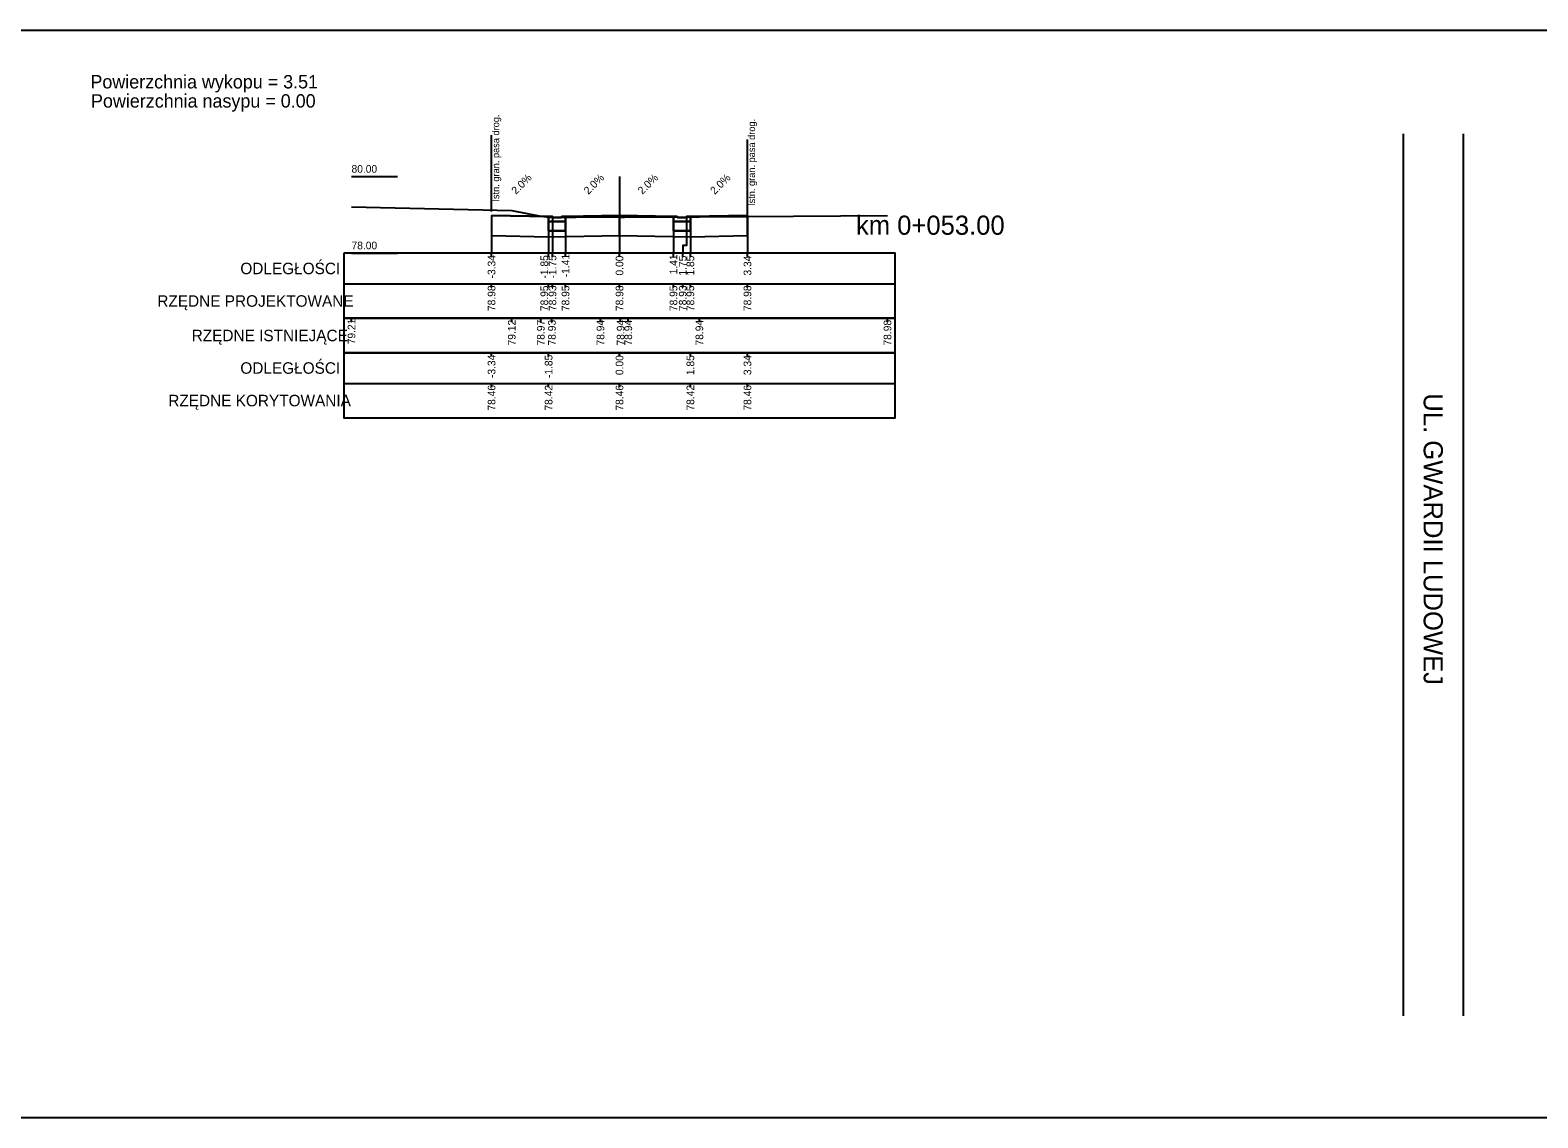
# Model space of a CAD drawing. Extents: x 7492871 to 7493499, y 5802964 to 5802992.
# Drawn here: x 7493262.74 to 7493302.12, y 5802963.88 to 5802992.28 of the extents above; entities that cross this region are included whole.
import ezdxf

# ---------------------------------------------------------------- set-up
doc = ezdxf.new("R2010")
doc.units = 0
for name, color, linetype in [('_wydruk', 7, 'Continuous'), ('d_pop_nasyp_opis', 7, 'Continuous'), ('d_pop_wykop_opis', 7, 'Continuous'), ('opisy_ramki_pop', 7, 'Continuous'), ('pop_comp_kostka', 7, 'Continuous'), ('pop_comp_lawa', 7, 'Continuous'), ('pop_comp_scieralna', 7, 'Continuous'), ('pop_granica_istn', 7, 'Continuous'), ('pop_opis', 7, 'Continuous'), ('pop_os', 7, 'Continuous'), ('pop_pikietaz', 7, 'Continuous'), ('pop_teren', 7, 'Continuous')]:
    doc.layers.add(name, color=color, linetype=linetype)

msp = doc.modelspace()

# ---------------------------------------------------------------- linework, layer by layer
msp.add_lwpolyline([(7493274.794, 5802987.442), (7493276.285, 5802987.413), (7493276.385, 5802987.413), (7493276.386, 5802987.393), (7493276.625, 5802987.393), (7493276.626, 5802987.413), (7493276.726, 5802987.413), (7493278.136, 5802987.441), (7493279.546, 5802987.413), (7493279.646, 5802987.413), (7493279.647, 5802987.393), (7493279.886, 5802987.393), (7493279.887, 5802987.413), (7493279.987, 5802987.413), (7493281.478, 5802987.442)])
at = {"layer": '_wydruk'}
msp.add_lwpolyline([(7492871.369, 5802992.281), (7493499.283, 5802992.281), (7493499.283, 5802963.881), (7492871.369, 5802963.881)], close=True, dxfattribs=at)
at = {"layer": 'opisy_ramki_pop'}
for p, q in [((7493298.607, 5802989.573), (7493298.607, 5802966.547)), ((7493300.173, 5802989.573), (7493300.173, 5802966.547))]:
    msp.add_line(p, q, dxfattribs=at)
for points in [[(7493274.794, 5802986.922), (7493274.794, 5802986.659), (7493274.794, 5802986.659), (7493274.794, 5802986.459)], [(7493276.285, 5802986.884), (7493276.285, 5802986.659), (7493276.285, 5802986.659), (7493276.285, 5802986.459)], [(7493278.136, 5802986.921), (7493278.136, 5802986.659), (7493278.136, 5802986.659), (7493278.136, 5802986.459)], [(7493279.987, 5802986.884), (7493279.987, 5802986.659), (7493279.987, 5802986.659), (7493279.987, 5802986.459)], [(7493281.478, 5802986.922), (7493281.478, 5802986.659), (7493281.478, 5802986.659), (7493281.478, 5802986.459)]]:
    msp.add_lwpolyline(points, dxfattribs=at)
at = {"layer": 'pop_comp_kostka'}
for p, q in [((7493276.385, 5802987.413), (7493276.285, 5802987.413)), ((7493276.285, 5802987.413), (7493276.285, 5802987.283)), ((7493276.386, 5802987.393), (7493276.385, 5802987.413)), ((7493276.625, 5802987.393), (7493276.386, 5802987.393)), ((7493276.626, 5802987.413), (7493276.625, 5802987.393)), ((7493276.726, 5802987.413), (7493276.626, 5802987.413)), ((7493276.726, 5802987.283), (7493276.726, 5802987.413)), ((7493279.646, 5802987.413), (7493279.546, 5802987.413)), ((7493279.546, 5802987.413), (7493279.546, 5802987.283)), ((7493279.647, 5802987.393), (7493279.646, 5802987.413)), ((7493279.886, 5802987.393), (7493279.647, 5802987.393)), ((7493279.887, 5802987.413), (7493279.886, 5802987.393)), ((7493279.987, 5802987.413), (7493279.887, 5802987.413)), ((7493279.987, 5802987.283), (7493279.987, 5802987.413)), ((7493276.285, 5802987.283), (7493276.726, 5802987.283)), ((7493279.546, 5802987.283), (7493279.987, 5802987.283))]:
    msp.add_line(p, q, dxfattribs=at)
at = {"layer": 'pop_comp_lawa'}
for p, q in [((7493276.726, 5802987.283), (7493276.285, 5802987.283)), ((7493276.285, 5802987.283), (7493276.285, 5802987.042)), ((7493276.285, 5802987.042), (7493276.726, 5802987.042)), ((7493276.726, 5802987.042), (7493276.726, 5802987.283)), ((7493279.987, 5802987.283), (7493279.546, 5802987.283)), ((7493279.546, 5802987.283), (7493279.546, 5802987.042)), ((7493279.546, 5802987.042), (7493279.987, 5802987.042)), ((7493279.987, 5802987.042), (7493279.987, 5802987.283))]:
    msp.add_line(p, q, dxfattribs=at)
at = {"layer": 'pop_comp_scieralna'}
for p, q in [((7493276.285, 5802987.413), (7493274.794, 5802987.442)), ((7493274.794, 5802987.442), (7493274.794, 5802986.922)), ((7493276.285, 5802987.042), (7493276.285, 5802987.413)), ((7493278.136, 5802987.441), (7493276.726, 5802987.413)), ((7493276.726, 5802987.413), (7493276.726, 5802987.042)), ((7493278.136, 5802986.921), (7493278.136, 5802987.441)), ((7493279.546, 5802987.413), (7493278.136, 5802987.441)), ((7493278.136, 5802987.441), (7493278.136, 5802986.921)), ((7493279.546, 5802987.042), (7493279.546, 5802987.413)), ((7493281.478, 5802987.442), (7493279.987, 5802987.413)), ((7493279.987, 5802987.413), (7493279.987, 5802987.042)), ((7493281.478, 5802986.922), (7493281.478, 5802987.442)), ((7493276.726, 5802987.042), (7493276.285, 5802987.042)), ((7493279.987, 5802987.042), (7493279.546, 5802987.042)), ((7493274.794, 5802986.922), (7493276.285, 5802986.884)), ((7493276.285, 5802986.884), (7493278.136, 5802986.921)), ((7493278.136, 5802986.921), (7493279.987, 5802986.884)), ((7493279.987, 5802986.884), (7493281.478, 5802986.922))]:
    msp.add_line(p, q, dxfattribs=at)
at = {"layer": 'pop_granica_istn'}
for p, q in [((7493274.794, 5802988.043), (7493274.794, 5802989.543)), ((7493281.478, 5802987.928), (7493281.478, 5802989.428)), ((7493274.794, 5802987.543), (7493274.794, 5802988.043)), ((7493281.478, 5802987.428), (7493281.478, 5802987.928))]:
    msp.add_line(p, q, dxfattribs=at)
at = {"layer": 'pop_opis'}
for p, q in [((7493271.136, 5802988.459), (7493272.336, 5802988.459)), ((7493270.936, 5802986.459), (7493270.936, 5802984.759)), ((7493270.936, 5802986.459), (7493270.936, 5802984.759)), ((7493270.936, 5802986.459), (7493270.936, 5802984.759)), ((7493270.936, 5802986.459), (7493270.936, 5802984.759)), ((7493271.136, 5802986.459), (7493272.336, 5802986.459)), ((7493274.794, 5802986.359), (7493274.794, 5802986.459)), ((7493276.285, 5802986.359), (7493276.285, 5802986.459)), ((7493276.386, 5802986.359), (7493276.386, 5802986.459)), ((7493276.726, 5802986.359), (7493276.726, 5802986.459)), ((7493278.136, 5802986.359), (7493278.136, 5802986.459)), ((7493279.546, 5802986.359), (7493279.546, 5802986.459)), ((7493279.787, 5802986.359), (7493279.787, 5802986.459)), ((7493279.987, 5802986.359), (7493279.987, 5802986.459)), ((7493281.478, 5802986.359), (7493281.478, 5802986.459)), ((7493270.936, 5802985.659), (7493285.336, 5802985.659)), ((7493270.936, 5802985.659), (7493285.336, 5802985.659)), ((7493270.936, 5802985.659), (7493285.336, 5802985.659)), ((7493270.936, 5802985.659), (7493285.336, 5802985.659)), ((7493274.794, 5802985.559), (7493274.794, 5802985.659)), ((7493276.285, 5802985.559), (7493276.285, 5802985.659)), ((7493276.386, 5802985.559), (7493276.386, 5802985.659)), ((7493276.726, 5802985.559), (7493276.726, 5802985.659)), ((7493278.136, 5802985.559), (7493278.136, 5802985.659)), ((7493279.546, 5802985.559), (7493279.546, 5802985.659)), ((7493279.787, 5802985.559), (7493279.787, 5802985.659)), ((7493279.987, 5802985.559), (7493279.987, 5802985.659)), ((7493281.478, 5802985.559), (7493281.478, 5802985.659)), ((7493270.936, 5802984.759), (7493270.936, 5802983.859)), ((7493271.136, 5802984.659), (7493271.136, 5802984.759)), ((7493275.322, 5802984.659), (7493275.322, 5802984.759)), ((7493276.08, 5802984.659), (7493276.08, 5802984.759)), ((7493276.37, 5802984.659), (7493276.37, 5802984.759)), ((7493277.638, 5802984.659), (7493277.638, 5802984.759)), ((7493278.165, 5802984.659), (7493278.165, 5802984.759)), ((7493278.365, 5802984.659), (7493278.365, 5802984.759)), ((7493280.222, 5802984.659), (7493280.222, 5802984.759)), ((7493285.136, 5802984.659), (7493285.136, 5802984.759)), ((7493270.936, 5802983.859), (7493270.936, 5802982.159)), ((7493274.794, 5802983.759), (7493274.794, 5802983.859)), ((7493276.285, 5802983.759), (7493276.285, 5802983.859)), ((7493278.136, 5802983.759), (7493278.136, 5802983.859)), ((7493279.987, 5802983.759), (7493279.987, 5802983.859)), ((7493281.478, 5802983.759), (7493281.478, 5802983.859)), ((7493270.936, 5802983.059), (7493285.336, 5802983.059)), ((7493274.794, 5802982.959), (7493274.794, 5802983.059)), ((7493276.285, 5802982.959), (7493276.285, 5802983.059)), ((7493278.136, 5802982.959), (7493278.136, 5802983.059)), ((7493279.987, 5802982.959), (7493279.987, 5802983.059)), ((7493281.478, 5802982.959), (7493281.478, 5802983.059))]:
    msp.add_line(p, q, dxfattribs=at)
for points in [[(7493274.794, 5802987.442), (7493274.794, 5802986.659), (7493274.794, 5802986.659), (7493274.794, 5802986.459)], [(7493276.285, 5802987.413), (7493276.285, 5802986.659), (7493276.285, 5802986.659), (7493276.285, 5802986.459)], [(7493276.386, 5802987.393), (7493276.386, 5802986.659), (7493276.386, 5802986.659), (7493276.386, 5802986.459)], [(7493276.726, 5802987.413), (7493276.726, 5802986.659), (7493276.726, 5802986.659), (7493276.726, 5802986.459)], [(7493278.136, 5802987.441), (7493278.136, 5802986.659), (7493278.136, 5802986.659), (7493278.136, 5802986.459)], [(7493279.546, 5802987.413), (7493279.546, 5802986.659), (7493279.546, 5802986.659), (7493279.546, 5802986.459)], [(7493279.886, 5802987.393), (7493279.886, 5802986.659), (7493279.787, 5802986.659), (7493279.787, 5802986.459)], [(7493279.987, 5802987.413), (7493279.987, 5802986.659), (7493279.987, 5802986.659), (7493279.987, 5802986.459)], [(7493281.478, 5802987.442), (7493281.478, 5802986.659), (7493281.478, 5802986.659), (7493281.478, 5802986.459)]]:
    msp.add_lwpolyline(points, dxfattribs=at)
for points in [[(7493270.936, 5802986.459), (7493270.936, 5802984.759), (7493285.336, 5802984.759), (7493285.336, 5802986.459)], [(7493270.936, 5802986.459), (7493270.936, 5802984.759), (7493285.336, 5802984.759), (7493285.336, 5802986.459)], [(7493270.936, 5802986.459), (7493270.936, 5802984.759), (7493285.336, 5802984.759), (7493285.336, 5802986.459)], [(7493270.936, 5802986.459), (7493270.936, 5802984.759), (7493285.336, 5802984.759), (7493285.336, 5802986.459)], [(7493270.936, 5802984.759), (7493270.936, 5802983.859), (7493285.336, 5802983.859), (7493285.336, 5802984.759)], [(7493270.936, 5802983.859), (7493270.936, 5802982.159), (7493285.336, 5802982.159), (7493285.336, 5802983.859)]]:
    msp.add_lwpolyline(points, close=True, dxfattribs=at)
at = {"layer": 'pop_os'}
msp.add_line((7493278.136, 5802988.459), (7493278.136, 5802986.459), dxfattribs=at)
at = {"layer": 'pop_teren'}
msp.add_lwpolyline([(7493271.136, 5802987.665), (7493275.322, 5802987.576), (7493276.08, 5802987.428), (7493276.37, 5802987.387), (7493277.638, 5802987.403), (7493278.165, 5802987.399), (7493278.27, 5802987.4), (7493280.222, 5802987.404), (7493285.136, 5802987.442)], dxfattribs=at)

# ---------------------------------------------------------------- texts
at = {"layer": 'd_pop_nasyp_opis'}
msp.add_text('Powierzchnia nasypu = 0.00', height=0.35, dxfattribs=at).set_placement((7493264.331, 5802990.259))
at = {"layer": 'd_pop_wykop_opis'}
msp.add_text('Powierzchnia wykopu = 3.51', height=0.35, dxfattribs=at).set_placement((7493264.316, 5802990.759))
at = {"layer": 'pop_granica_istn'}
for p in [(7493274.993, 5802987.804), (7493281.677, 5802987.69)]:
    msp.add_text('Istn. gran. pasa drog.', height=0.18, rotation=90, dxfattribs=at).set_placement(p)
at = {"layer": 'pop_opis'}
for s, height, p in [('80.00', 0.2, (7493271.136, 5802988.559)), ('78.00', 0.2, (7493271.136, 5802986.559)), ('ODLEGŁOŚCI', 0.3, (7493268.232, 5802985.909)), ('ODLEGŁOŚCI', 0.3, (7493268.232, 5802985.909)), ('ODLEGŁOŚCI', 0.3, (7493268.232, 5802985.909)), ('ODLEGŁOŚCI', 0.3, (7493268.232, 5802985.909)), ('RZĘDNE PROJEKTOWANE', 0.3, (7493266.064, 5802985.059)), ('RZĘDNE PROJEKTOWANE', 0.3, (7493266.064, 5802985.059)), ('RZĘDNE PROJEKTOWANE', 0.3, (7493266.064, 5802985.059)), ('RZĘDNE PROJEKTOWANE', 0.3, (7493266.064, 5802985.059)), ('RZĘDNE ISTNIEJĄCE', 0.3, (7493266.961, 5802984.159)), ('ODLEGŁOŚCI', 0.3, (7493268.232, 5802983.309)), ('RZĘDNE KORYTOWANIA', 0.3, (7493266.35, 5802982.459))]:
    msp.add_text(s, height=height, dxfattribs=at).set_placement(p)
for s, rotation, p in [('2.0%', 45, (7493275.431, 5802987.977)), ('2.0%', 45, (7493277.322, 5802987.977)), ('2.0%', 45, (7493278.732, 5802987.977)), ('2.0%', 45, (7493280.624, 5802987.977)), ('-3.34', 90, (7493274.894, 5802985.798)), ('-1.85', 90, (7493276.272, 5802985.796)), ('-1.75', 90, (7493276.486, 5802985.796)), ('-1.41', 90, (7493276.826, 5802985.829)), ('0.00', 90, (7493278.236, 5802985.874)), ('1.41', 90, (7493279.646, 5802985.905)), ('1.75', 90, (7493279.887, 5802985.873)), ('1.85', 90, (7493280.087, 5802985.873)), ('3.34', 90, (7493281.578, 5802985.874)), ('78.98', 90, (7493274.894, 5802984.946)), ('78.95', 90, (7493276.272, 5802984.945)), ('78.93', 90, (7493276.486, 5802984.947)), ('78.95', 90, (7493276.826, 5802984.945)), ('78.98', 90, (7493278.236, 5802984.946)), ('78.95', 90, (7493279.646, 5802984.945)), ('78.93', 90, (7493279.887, 5802984.947)), ('78.95', 90, (7493280.087, 5802984.945)), ('78.98', 90, (7493281.578, 5802984.946)), ('79.21', 90, (7493271.236, 5802984.078)), ('79.12', 90, (7493275.422, 5802984.048)), ('78.97', 90, (7493276.18, 5802984.047)), ('78.93', 90, (7493276.47, 5802984.047)), ('78.94', 90, (7493277.738, 5802984.047)), ('78.94', 90, (7493278.265, 5802984.047)), ('78.94', 90, (7493278.465, 5802984.047)), ('78.94', 90, (7493280.322, 5802984.047)), ('78.98', 90, (7493285.236, 5802984.046)), ('-3.34', 90, (7493274.894, 5802983.198)), ('-1.85', 90, (7493276.385, 5802983.196)), ('0.00', 90, (7493278.236, 5802983.274)), ('1.85', 90, (7493280.087, 5802983.273)), ('3.34', 90, (7493281.578, 5802983.274)), ('78.46', 90, (7493274.894, 5802982.347)), ('78.42', 90, (7493276.385, 5802982.348)), ('78.46', 90, (7493278.236, 5802982.347)), ('78.42', 90, (7493280.087, 5802982.348)), ('78.46', 90, (7493281.578, 5802982.347))]:
    msp.add_text(s, height=0.2, rotation=rotation, dxfattribs=at).set_placement(p)
at = {"layer": 'pop_pikietaz'}
msp.add_text('km 0+053.00', height=0.5, dxfattribs=at).set_placement((7493284.313, 5802986.939))
msp.add_text('UL. GWARDII LUDOWEJ', height=0.5, rotation=270, dxfattribs=at).set_placement((7493299.141, 5802982.798))

doc.saveas('drawing.dxf')
